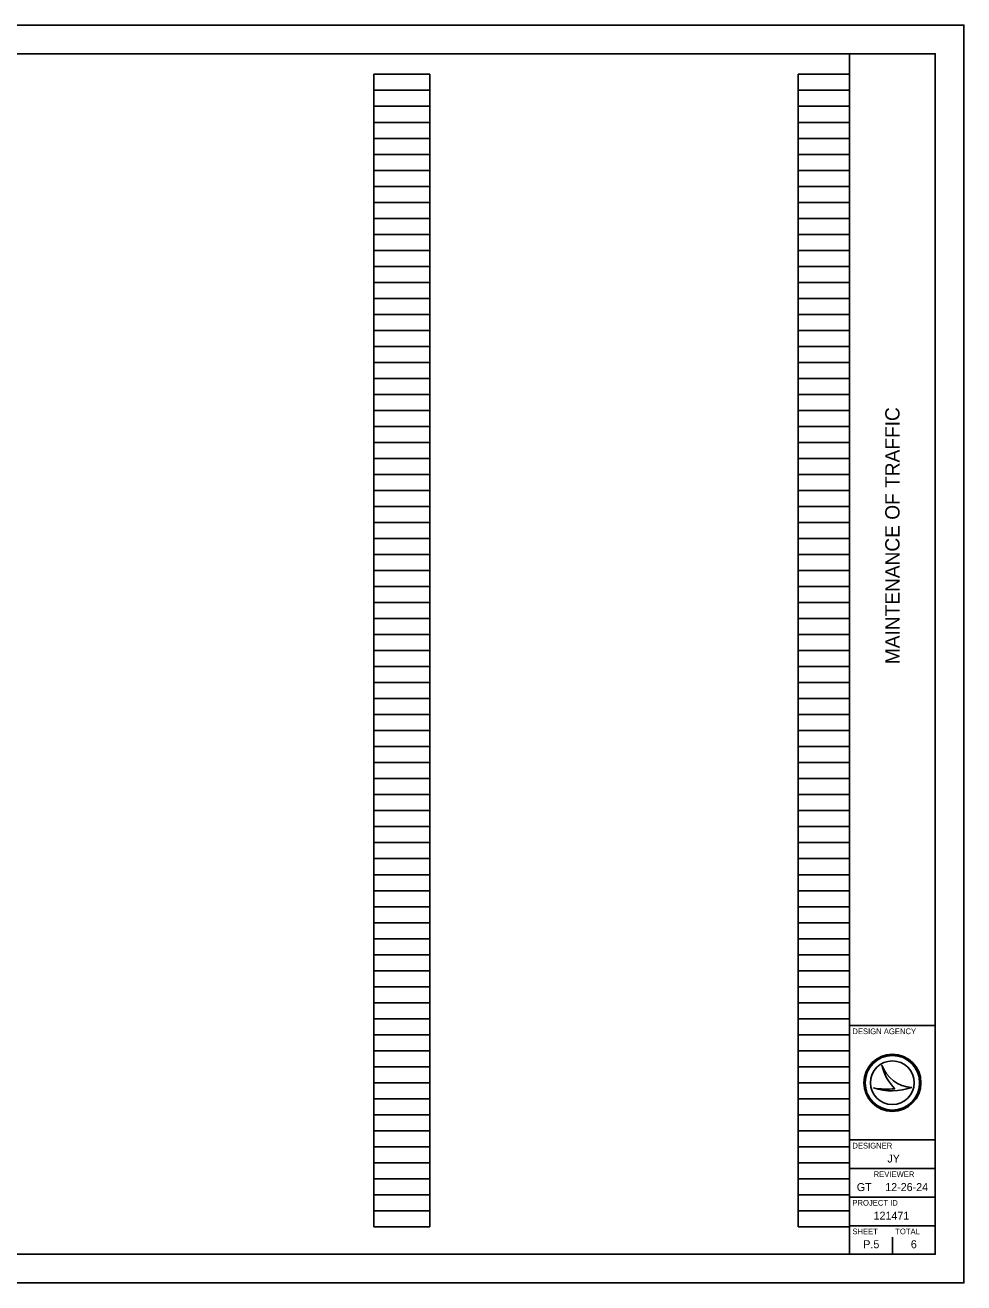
# Model space of a CAD drawing. Extents: x 0 to 34, y -7.4 to 22.
# Drawn here: x 17.58 to 34, y 0 to 22 of the extents above; entities that cross this region are included whole.
import ezdxf

# ---------------------------------------------------------------- set-up
doc = ezdxf.new("R2010")
doc.units = 0
for name, color, linetype in [('SH_Border', 7, 'Continuous'), ('SH_Cut_Line', 7, 'Continuous'), ('SH_Data', 7, 'Continuous')]:
    doc.layers.add(name, color=color, linetype=linetype)

msp = doc.modelspace()

# ---------------------------------------------------------------- linework, layer by layer
at = {"layer": 'SH_Border'}
for p, q in [((32, 0.5), (32, 21.5)), ((32, 4.5), (33.5, 4.5)), ((32, 2.5), (33.5, 2.5)), ((32, 2), (33.5, 2)), ((32, 1.5), (33.5, 1.5)), ((32, 1), (33.5, 1))]:
    msp.add_line(p, q, dxfattribs=at)
msp.add_lwpolyline([(1.5, 21.5), (33.5, 21.5), (33.5, 0.5), (1.5, 0.5)], close=True, dxfattribs=at)
at = {"layer": 'SH_Cut_Line'}
msp.add_lwpolyline([(0, 0), (34, 0), (34, 22), (0, 22)], close=True, dxfattribs=at)
at = {"layer": 'SH_Data'}
for p, q in [((23.68, 0.98), (23.68, 21.14)), ((23.68, 21.14), (24.66, 21.14)), ((24.66, 0.98), (24.66, 21.14)), ((31.1, 0.98), (31.1, 21.14)), ((31.1, 21.14), (32, 21.14)), ((32, 0.98), (32, 21.14)), ((23.68, 20.86), (24.66, 20.86)), ((31.1, 20.86), (32, 20.86)), ((23.68, 20.58), (24.66, 20.58)), ((31.1, 20.58), (32, 20.58)), ((23.68, 20.3), (24.66, 20.3)), ((31.1, 20.3), (32, 20.3)), ((23.68, 20.02), (24.66, 20.02)), ((31.1, 20.02), (32, 20.02)), ((23.68, 19.74), (24.66, 19.74)), ((31.1, 19.74), (32, 19.74)), ((23.68, 19.46), (24.66, 19.46)), ((31.1, 19.46), (32, 19.46)), ((23.68, 19.18), (24.66, 19.18)), ((31.1, 19.18), (32, 19.18)), ((23.68, 18.9), (24.66, 18.9)), ((31.1, 18.9), (32, 18.9)), ((23.68, 18.62), (24.66, 18.62)), ((31.1, 18.62), (32, 18.62)), ((23.68, 18.34), (24.66, 18.34)), ((31.1, 18.34), (32, 18.34)), ((23.68, 18.06), (24.66, 18.06)), ((31.1, 18.06), (32, 18.06)), ((23.68, 17.78), (24.66, 17.78)), ((31.1, 17.78), (32, 17.78)), ((23.68, 17.5), (24.66, 17.5)), ((31.1, 17.5), (32, 17.5)), ((23.68, 17.22), (24.66, 17.22)), ((31.1, 17.22), (32, 17.22)), ((23.68, 16.94), (24.66, 16.94)), ((31.1, 16.94), (32, 16.94)), ((23.68, 16.66), (24.66, 16.66)), ((31.1, 16.66), (32, 16.66)), ((23.68, 16.38), (24.66, 16.38)), ((31.1, 16.38), (32, 16.38)), ((23.68, 16.1), (24.66, 16.1)), ((31.1, 16.1), (32, 16.1)), ((23.68, 15.82), (24.66, 15.82)), ((31.1, 15.82), (32, 15.82)), ((23.68, 15.54), (24.66, 15.54)), ((31.1, 15.54), (32, 15.54)), ((23.68, 15.26), (24.66, 15.26)), ((31.1, 15.26), (32, 15.26)), ((23.68, 14.98), (24.66, 14.98)), ((31.1, 14.98), (32, 14.98)), ((23.68, 14.7), (24.66, 14.7)), ((31.1, 14.7), (32, 14.7)), ((23.68, 14.42), (24.66, 14.42)), ((31.1, 14.42), (32, 14.42)), ((23.68, 14.14), (24.66, 14.14)), ((31.1, 14.14), (32, 14.14)), ((23.68, 13.86), (24.66, 13.86)), ((31.1, 13.86), (32, 13.86)), ((23.68, 13.58), (24.66, 13.58)), ((31.1, 13.58), (32, 13.58)), ((23.68, 13.3), (24.66, 13.3)), ((31.1, 13.3), (32, 13.3)), ((23.68, 13.02), (24.66, 13.02)), ((31.1, 13.02), (32, 13.02)), ((23.68, 12.74), (24.66, 12.74)), ((31.1, 12.74), (32, 12.74)), ((23.68, 12.46), (24.66, 12.46)), ((31.1, 12.46), (32, 12.46)), ((23.68, 12.18), (24.66, 12.18)), ((31.1, 12.18), (32, 12.18)), ((23.68, 11.9), (24.66, 11.9)), ((31.1, 11.9), (32, 11.9)), ((23.68, 11.62), (24.66, 11.62)), ((31.1, 11.62), (32, 11.62)), ((23.68, 11.34), (24.66, 11.34)), ((31.1, 11.34), (32, 11.34)), ((23.68, 11.06), (24.66, 11.06)), ((31.1, 11.06), (32, 11.06)), ((23.68, 10.78), (24.66, 10.78)), ((31.1, 10.78), (32, 10.78)), ((23.68, 10.5), (24.66, 10.5)), ((31.1, 10.5), (32, 10.5)), ((23.68, 10.22), (24.66, 10.22)), ((31.1, 10.22), (32, 10.22)), ((23.68, 9.94), (24.66, 9.94)), ((31.1, 9.94), (32, 9.94)), ((23.68, 9.66), (24.66, 9.66)), ((31.1, 9.66), (32, 9.66)), ((23.68, 9.38), (24.66, 9.38)), ((31.1, 9.38), (32, 9.38)), ((23.68, 9.1), (24.66, 9.1)), ((31.1, 9.1), (32, 9.1)), ((23.68, 8.82), (24.66, 8.82)), ((31.1, 8.82), (32, 8.82)), ((23.68, 8.54), (24.66, 8.54)), ((31.1, 8.54), (32, 8.54)), ((23.68, 8.26), (24.66, 8.26)), ((31.1, 8.26), (32, 8.26)), ((23.68, 7.98), (24.66, 7.98)), ((31.1, 7.98), (32, 7.98)), ((23.68, 7.7), (24.66, 7.7)), ((31.1, 7.7), (32, 7.7)), ((23.68, 7.42), (24.66, 7.42)), ((31.1, 7.42), (32, 7.42)), ((23.68, 7.14), (24.66, 7.14)), ((31.1, 7.14), (32, 7.14)), ((23.68, 6.86), (24.66, 6.86)), ((31.1, 6.86), (32, 6.86)), ((23.68, 6.58), (24.66, 6.58)), ((31.1, 6.58), (32, 6.58)), ((23.68, 6.3), (24.66, 6.3)), ((31.1, 6.3), (32, 6.3)), ((23.68, 6.02), (24.66, 6.02)), ((31.1, 6.02), (32, 6.02)), ((23.68, 5.74), (24.66, 5.74)), ((31.1, 5.74), (32, 5.74)), ((23.68, 5.46), (24.66, 5.46)), ((31.1, 5.46), (32, 5.46)), ((23.68, 5.18), (24.66, 5.18)), ((31.1, 5.18), (32, 5.18)), ((23.68, 4.9), (24.66, 4.9)), ((31.1, 4.9), (32, 4.9)), ((23.68, 4.62), (24.66, 4.62)), ((31.1, 4.62), (32, 4.62)), ((23.68, 4.34), (24.66, 4.34)), ((31.1, 4.34), (32, 4.34)), ((23.68, 4.06), (24.66, 4.06)), ((31.1, 4.06), (32, 4.06)), ((23.68, 3.78), (24.66, 3.78)), ((31.1, 3.78), (32, 3.78)), ((32.567, 3.81), (32.567, 3.81)), ((23.68, 3.5), (24.66, 3.5)), ((31.1, 3.5), (32, 3.5)), ((32.417, 3.41), (32.417, 3.41)), ((32.75, 3.5), (32.75, 3.5)), ((33.087, 3.419), (33.087, 3.419)), ((23.68, 3.22), (24.66, 3.22)), ((31.1, 3.22), (32, 3.22)), ((23.68, 2.94), (24.66, 2.94)), ((31.1, 2.94), (32, 2.94)), ((23.68, 2.66), (24.66, 2.66)), ((31.1, 2.66), (32, 2.66)), ((23.68, 2.38), (24.66, 2.38)), ((31.1, 2.38), (32, 2.38)), ((23.68, 2.1), (24.66, 2.1)), ((31.1, 2.1), (32, 2.1)), ((23.68, 1.82), (24.66, 1.82)), ((31.1, 1.82), (32, 1.82)), ((23.68, 1.54), (24.66, 1.54)), ((31.1, 1.54), (32, 1.54)), ((23.68, 1.26), (24.66, 1.26)), ((31.1, 1.26), (32, 1.26)), ((23.68, 0.98), (24.66, 0.98)), ((31.1, 0.98), (32, 0.98)), ((32.375, 0.675), (32.375, 0.675)), ((32.75, 0.5), (32.75, 0.8))]:
    msp.add_line(p, q, dxfattribs=at)
for radius in [0.5, 0.477, 0.477, 0.382]:
    msp.add_circle((32.75, 3.5), radius, dxfattribs=at)
for centre, radius, start, end in [((33.116, 3.998), 0.58, 198.9257, 198.9319), ((33.347, 3.97), 0.796, 191.6379, 191.6421), ((33.116, 3.998), 0.58, 198.9319, 267.1657), ((33.347, 3.97), 0.796, 191.6421, 226.0947), ((32.739, 4.37), 1.013, 251.4576, 290.0832), ((32.648, 4.654), 1.266, 259.4964, 259.4995), ((32.739, 4.37), 1.013, 251.4527, 251.4576), ((32.648, 4.654), 1.266, 259.4995, 276.6672)]:
    msp.add_arc(centre, radius, start, end, dxfattribs=at)

# ---------------------------------------------------------------- texts
msp.add_text('MAINTENANCE OF TRAFFIC', height=0.25, rotation=90, dxfattribs=at).set_placement((32.875, 10.822))
for s, height, p in [('DESIGN AGENCY', 0.1, (32.05, 4.35)), ('DESIGNER', 0.1, (32.05, 2.35)), ('JY', 0.14, (32.663, 2.105)), ('REVIEWER', 0.1, (32.422, 1.85)), ('GT', 0.14, (32.128, 1.605)), ('12-26-24', 0.14, (32.625, 1.605)), ('PROJECT ID', 0.1, (32.05, 1.35)), ('121471', 0.14, (32.421, 1.105)), ('SHEET', 0.1, (32.05, 0.85)), ('TOTAL', 0.1, (32.8, 0.85)), ('P.5', 0.14, (32.241, 0.605)), ('6', 0.14, (33.073, 0.605))]:
    msp.add_text(s, height=height, dxfattribs=at).set_placement(p)

doc.saveas('drawing.dxf')
